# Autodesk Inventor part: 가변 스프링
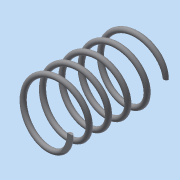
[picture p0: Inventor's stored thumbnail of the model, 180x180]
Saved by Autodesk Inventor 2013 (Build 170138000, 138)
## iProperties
Created: 2015-10
Part Number: 가변 스프링
Material: 일반
Document SubType Name: Modeling
Designer: Administrator
Density: 1 g/cm^3
Author: Administrator
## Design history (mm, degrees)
sketch "스케치1"
  geometry: L1 (0, 0)-(0, 18.948); L2 (0, 0)-(5.5, 0); L3 (0, 18.948)-(5.5, 18.948); C1 r 0.5 at (5.5, 0)
  constraints: 6 end point, 1 centre point, 1 horizontal alignment, 1 parallel, 1 perpendicular, 1 vertical
  dimensions: "d0" = 18.94782 distance of L1.start L1.end (derived); "d1" = 1 diameter of C1; "d2" = 11 diameter of L2.end L1
feature "코일1" sketch "스케치1" pitch "d3" = 10; turns "d5" = 5; dims "d4" = 18.94782 (= d0), "d6" = 0, angle "d7" = 90 deg, angle "d8" = 90 deg, "d9" = 0, "d10" = 0
sketch "스케치2"
  geometry: L1 (0, 6.5)-(18.948, 6.5); L2 (18.948, 6.5)-(18.948, -6.5); L3 (18.948, -6.5)-(0, -6.5); L4 (0, -6.5)-(0, 6.5); 2 further points
  constraints: 8 end point, 2 parallel, 1 coincident, 1 horizontal, 1 midpoint, 1 perpendicular
  dimensions: "d11" = 18.94782 distance of L2.end L3.end (derived); "d13" = 13 distance of L1.end L2.end
extrude "돌출1" sketch "스케치2" stored distance "d14" = 0; taper "d15" = 0 deg
node "솔리드1"
